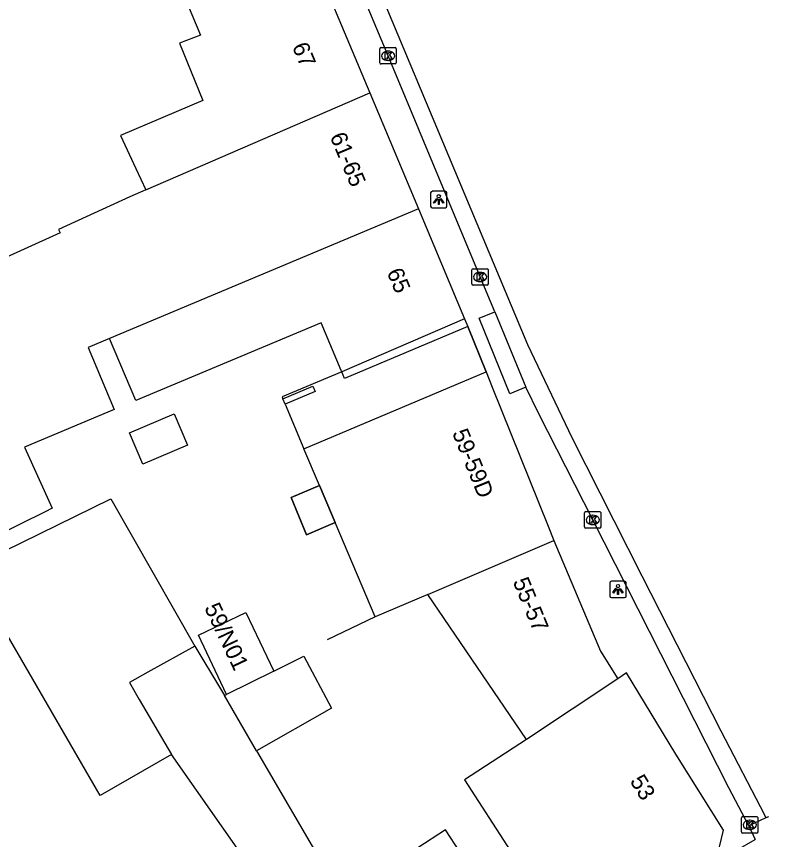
# Model space of a CAD drawing. Extents: x 159377 to 159983, y 382996 to 383595.
# Drawn here: x 159936.99 to 159982.64, y 383295.81 to 383345.77 of the extents above; entities that cross this region are included whole.
import ezdxf

# ---------------------------------------------------------------- set-up
doc = ezdxf.new("R2010")
doc.units = 0
for name, color, linetype in [('IMGEO_Kolk', 7, 'Continuous'), ('IMGEO_Lichtpunt', 7, 'Continuous'), ('IMGEO_Muur', 7, 'Continuous'), ('IMGEO_Pand', 7, 'Continuous'), ('IMGEO_Pand_nummerreeks', 7, 'Continuous'), ('IMGEO_Pand_overbouw', 7, 'Continuous'), ('IMGEO_Rijbaan_lokaal_gesloten', 7, 'Continuous'), ('IMGEO_Rijbaan_lokaal_open', 7, 'Continuous'), ('IMGEO_Voetpad_open', 7, 'Continuous')]:
    doc.layers.add(name, color=color, linetype=linetype)

msp = doc.modelspace()

# ---------------------------------------------------------------- linework, layer by layer
at = {"layer": 'IMGEO_Kolk'}
for p, q in [((159959.042, 383342.956), (159959.042, 383343.808)), ((159959.117, 383343.882), (159959.969, 383343.882)), ((159959.53, 383343.662), (159959.555, 383343.662)), ((159960.043, 383343.808), (159960.043, 383342.956)), ((159959.553, 383343.102), (159959.528, 383343.102)), ((159959.969, 383342.882), (159959.117, 383342.882)), ((159964.627, 383329.53), (159964.627, 383330.382)), ((159964.702, 383330.456), (159965.554, 383330.456)), ((159965.115, 383330.236), (159965.14, 383330.236)), ((159965.628, 383330.382), (159965.628, 383329.53)), ((159965.138, 383329.676), (159965.113, 383329.676)), ((159965.554, 383329.456), (159964.702, 383329.456)), ((159971.466, 383314.783), (159971.466, 383315.635)), ((159971.541, 383315.709), (159972.393, 383315.709)), ((159972.467, 383315.635), (159972.467, 383314.783)), ((159971.954, 383315.489), (159971.979, 383315.489)), ((159972.393, 383314.709), (159971.541, 383314.709)), ((159971.977, 383314.929), (159971.952, 383314.929)), ((159980.996, 383296.27), (159980.996, 383297.122)), ((159981.071, 383297.196), (159981.923, 383297.196)), ((159981.997, 383297.122), (159981.997, 383296.27)), ((159981.484, 383296.976), (159981.509, 383296.976)), ((159981.923, 383296.196), (159981.071, 383296.196)), ((159981.507, 383296.416), (159981.482, 383296.416))]:
    msp.add_line(p, q, dxfattribs=at)
for points in [[(159959.042, 383342.956), (159959.042, 383343.808)], [(159959.117, 383343.882), (159959.969, 383343.882)], [(159959.363, 383343.582), (159959.486, 383343.582), (159959.486, 383343.431), (159959.616, 383343.582), (159959.78, 383343.582), (159959.634, 383343.431), (159959.787, 383343.182), (159959.635, 383343.182), (159959.55, 383343.346), (159959.486, 383343.279), (159959.486, 383343.182), (159959.363, 383343.182), (159959.363, 383343.582)], [(159960.043, 383343.808), (159960.043, 383342.956)], [(159959.969, 383342.882), (159959.117, 383342.882)], [(159964.627, 383329.53), (159964.627, 383330.382)], [(159964.702, 383330.456), (159965.554, 383330.456)], [(159964.948, 383330.156), (159965.071, 383330.156), (159965.071, 383330.005), (159965.201, 383330.156), (159965.365, 383330.156), (159965.219, 383330.005), (159965.372, 383329.756), (159965.22, 383329.756), (159965.135, 383329.92), (159965.071, 383329.853), (159965.071, 383329.756), (159964.948, 383329.756), (159964.948, 383330.156)], [(159965.628, 383330.382), (159965.628, 383329.53)], [(159965.554, 383329.456), (159964.702, 383329.456)], [(159971.466, 383314.783), (159971.466, 383315.635)], [(159971.541, 383315.709), (159972.393, 383315.709)], [(159972.467, 383315.635), (159972.467, 383314.783)], [(159971.787, 383315.409), (159971.91, 383315.409), (159971.91, 383315.258), (159972.04, 383315.409), (159972.204, 383315.409), (159972.058, 383315.258), (159972.211, 383315.009), (159972.059, 383315.009), (159971.974, 383315.173), (159971.91, 383315.106), (159971.91, 383315.009), (159971.787, 383315.009), (159971.787, 383315.409)], [(159972.393, 383314.709), (159971.541, 383314.709)], [(159980.996, 383296.27), (159980.996, 383297.122)], [(159981.071, 383297.196), (159981.923, 383297.196)], [(159981.997, 383297.122), (159981.997, 383296.27)], [(159981.317, 383296.896), (159981.44, 383296.896), (159981.44, 383296.745), (159981.57, 383296.896), (159981.734, 383296.896), (159981.588, 383296.745), (159981.741, 383296.496), (159981.589, 383296.496), (159981.504, 383296.66), (159981.44, 383296.593), (159981.44, 383296.496), (159981.317, 383296.496), (159981.317, 383296.896)], [(159981.923, 383296.196), (159981.071, 383296.196)]]:
    msp.add_lwpolyline(points, dxfattribs=at)
for centre, start, end in [((159959.119, 383343.806), 91.552, 178.448), ((159959.119, 383343.806), 91.552, 178.448), ((159959.967, 383343.806), 1.552, 88.448), ((159959.967, 383343.806), 1.552, 88.448), ((159959.119, 383342.958), 181.552, 268.448), ((159959.119, 383342.958), 181.552, 268.448), ((159959.967, 383342.958), 271.552, 358.448), ((159959.967, 383342.958), 271.552, 358.448), ((159964.704, 383330.38), 91.552, 178.448), ((159964.704, 383330.38), 91.552, 178.448), ((159965.552, 383330.38), 1.552, 88.448), ((159965.552, 383330.38), 1.552, 88.448), ((159964.704, 383329.532), 181.552, 268.448), ((159964.704, 383329.532), 181.552, 268.448), ((159965.552, 383329.532), 271.552, 358.448), ((159965.552, 383329.532), 271.552, 358.448), ((159971.543, 383315.633), 91.552, 178.448), ((159971.543, 383315.633), 91.552, 178.448), ((159972.391, 383315.633), 1.552, 88.448), ((159972.391, 383315.633), 1.552, 88.448), ((159971.543, 383314.785), 181.552, 268.448), ((159971.543, 383314.785), 181.552, 268.448), ((159972.391, 383314.785), 271.552, 358.448), ((159972.391, 383314.785), 271.552, 358.448), ((159981.073, 383297.12), 91.552, 178.448), ((159981.073, 383297.12), 91.552, 178.448), ((159981.921, 383297.12), 1.552, 88.448), ((159981.921, 383297.12), 1.552, 88.448), ((159981.073, 383296.272), 181.552, 268.448), ((159981.073, 383296.272), 181.552, 268.448), ((159981.921, 383296.272), 271.552, 358.448), ((159981.921, 383296.272), 271.552, 358.448)]:
    msp.add_arc(centre, 0.0765, start, end, dxfattribs=at)
for centre, major_axis, ratio, start_param, end_param in [((159959.529, 383343.382), (-0.387, 0.002), 0.722429, 4.712389, 7.853982), ((159959.554, 383343.382), (-0.39, 0.002), 0.717154, 1.570796, 4.712389), ((159965.114, 383329.956), (-0.387, 0.002), 0.722429, 4.712389, 7.853982), ((159965.139, 383329.956), (-0.39, 0.002), 0.717154, 1.570796, 4.712389), ((159971.953, 383315.209), (-0.387, 0.002), 0.722429, 4.712389, 7.853982), ((159971.978, 383315.209), (-0.39, 0.002), 0.717154, 1.570796, 4.712389), ((159981.483, 383296.696), (-0.387, 0.002), 0.722429, 4.712389, 7.853982), ((159981.508, 383296.696), (-0.39, 0.002), 0.717154, 1.570796, 4.712389)]:
    msp.add_ellipse(centre, major_axis=major_axis, ratio=ratio, start_param=start_param, end_param=end_param, dxfattribs=at)
at = {"layer": 'IMGEO_Lichtpunt'}
for p, q in [((159962.122, 383335.058), (159962.122, 383334.251)), ((159962.122, 383335.058), (159962.122, 383334.251)), ((159963.024, 383335.153), (159962.216, 383335.153)), ((159963.024, 383335.153), (159962.216, 383335.153)), ((159963.118, 383334.251), (159963.118, 383335.058)), ((159963.118, 383334.251), (159963.118, 383335.058)), ((159962.216, 383334.157), (159963.024, 383334.157)), ((159962.216, 383334.157), (159963.024, 383334.157)), ((159973.001, 383311.392), (159973.001, 383310.585)), ((159973.001, 383311.392), (159973.001, 383310.585)), ((159973.903, 383311.487), (159973.095, 383311.487)), ((159973.903, 383311.487), (159973.095, 383311.487)), ((159973.997, 383310.585), (159973.997, 383311.392)), ((159973.997, 383310.585), (159973.997, 383311.392)), ((159973.095, 383310.491), (159973.903, 383310.491)), ((159973.095, 383310.491), (159973.903, 383310.491))]:
    msp.add_line(p, q, dxfattribs=at)
for points in [[(159962.496, 383334.722), (159962.535, 383334.694), (159962.347, 383334.432), (159962.309, 383334.459), (159962.496, 383334.722)], [(159962.598, 383334.674), (159962.645, 383334.674), (159962.645, 383334.352), (159962.598, 383334.352), (159962.598, 383334.674)], [(159962.708, 383334.694), (159962.746, 383334.721), (159962.933, 383334.459), (159962.894, 383334.431), (159962.708, 383334.694)], [(159973.375, 383311.056), (159973.414, 383311.028), (159973.226, 383310.766), (159973.188, 383310.793), (159973.375, 383311.056)], [(159973.477, 383311.008), (159973.524, 383311.008), (159973.524, 383310.686), (159973.477, 383310.686), (159973.477, 383311.008)], [(159973.587, 383311.028), (159973.625, 383311.055), (159973.812, 383310.793), (159973.773, 383310.765), (159973.587, 383311.028)]]:
    msp.add_lwpolyline(points, dxfattribs=at)
for centre in [(159962.621, 383334.856), (159973.5, 383311.19)]:
    msp.add_circle(centre, 0.0994, dxfattribs=at)
for centre, start, end in [((159962.216, 383335.058), 90, 180), ((159962.216, 383335.058), 90, 180), ((159963.024, 383335.058), 0, 90), ((159963.024, 383335.058), 0, 90), ((159962.216, 383334.251), 180, 270), ((159962.216, 383334.251), 180, 270), ((159963.024, 383334.251), 270, 0), ((159963.024, 383334.251), 270, 360), ((159973.095, 383311.392), 90, 180), ((159973.095, 383311.392), 90, 180), ((159973.903, 383311.392), 0, 90), ((159973.903, 383311.392), 0, 90), ((159973.095, 383310.585), 180, 270), ((159973.095, 383310.585), 180, 270), ((159973.903, 383310.585), 270, 0), ((159973.903, 383310.585), 270, 360)]:
    msp.add_arc(centre, 0.0946, start, end, dxfattribs=at)
at = {"layer": 'IMGEO_Muur'}
msp.add_lwpolyline([(159958.755, 383309.324), (159955.838, 383307.922)], dxfattribs=at)
at = {"layer": 'IMGEO_Pand'}
for points in [[(159952.848, 383354.454), (159955.649, 383347.779), (159958.438, 383341.13)], [(159945.365, 383351.314), (159948.165, 383344.639), (159946.882, 383344.151), (159948.29, 383340.671), (159943.299, 383338.535), (159944.236, 383336.532), (159944.843, 383335.234)], [(159944.843, 383335.234), (159958.438, 383341.13)], [(159958.438, 383341.13), (159961.392, 383334.091)], [(159944.843, 383335.234), (159943.863, 383334.809), (159939.54, 383332.832), (159939.633, 383332.626), (159933.064, 383329.657), (159932.987, 383329.817)], [(159961.392, 383334.091), (159942.64, 383326.223)], [(159961.392, 383334.091), (159964.191, 383327.419)], [(159956.726, 383324.201), (159956.696, 383324.274), (159955.478, 383327.179), (159944.228, 383322.46), (159942.64, 383326.223)], [(159964.191, 383327.419), (159956.726, 383324.201)], [(159964.191, 383327.419), (159964.378, 383326.953)], [(159964.378, 383326.953), (159956.901, 383323.786), (159956.726, 383324.201)], [(159942.64, 383326.223), (159941.338, 383325.677), (159942.926, 383321.914), (159937.464, 383319.623), (159939.155, 383315.913), (159938.725, 383315.702), (159934.236, 383313.5)], [(159955.38, 383317.291), (159954.438, 383319.517), (159965.489, 383324.198)], [(159965.489, 383324.198), (159965.863, 383323.269), (159969.264, 383314.829), (159969.612, 383313.966)], [(159953.299, 383322.228), (159953.163, 383322.55), (159954.981, 383323.32), (159955.117, 383322.998), (159953.299, 383322.228)], [(159943.845, 383320.503), (159946.558, 383321.648), (159947.362, 383319.744), (159944.649, 383318.599), (159943.845, 383320.503)], [(159955.38, 383317.291), (159956.332, 383315.043)], [(159934.071, 383312.263), (159942.713, 383316.486), (159947.811, 383307.547)], [(159961.953, 383310.678), (159958.755, 383309.324), (159956.332, 383315.043)], [(159961.953, 383310.678), (159969.612, 383313.966)], [(159969.612, 383313.966), (159972.441, 383307.245), (159973.493, 383305.565)], [(159967.948, 383301.873), (159961.953, 383310.678)], [(159949.745, 383304.614), (159948.027, 383308.209), (159950.905, 383309.585), (159952.605, 383306.029)], [(159946.404, 383300.967), (159942.065, 383298.484), (159936.196, 383308.615)], [(159947.811, 383307.547), (159944.953, 383305.96), (159943.837, 383305.341), (159944.439, 383304.314), (159946.404, 383300.967)], [(159947.811, 383307.547), (159949.364, 383304.957), (159949.605, 383304.544)], [(159952.605, 383306.029), (159954.438, 383306.935), (159956.105, 383303.788), (159951.562, 383301.19)], [(159952.605, 383306.029), (159949.745, 383304.614)], [(159979.443, 383294.433), (159979.906, 383296.377), (159977.007, 383300.995), (159974.015, 383305.934), (159973.493, 383305.565)], [(159973.493, 383305.565), (159967.948, 383301.873)], [(159949.605, 383304.544), (159949.745, 383304.614)], [(159951.562, 383301.19), (159949.605, 383304.544)], [(159967.948, 383301.873), (159964.186, 383299.423), (159966.951, 383295.149)], [(159951.562, 383301.19), (159955.785, 383293.954), (159952.607, 383292.1), (159946.404, 383300.967)], [(159966.951, 383295.149), (159964.76, 383293.732), (159963.033, 383296.402), (159961.344, 383295.309)]]:
    msp.add_lwpolyline(points, dxfattribs=at)
at = {"layer": 'IMGEO_Pand_overbouw'}
for points in [[(159956.726, 383324.201), (159953.109, 383322.679), (159953.163, 383322.55), (159954.981, 383323.32), (159955.117, 383322.998), (159953.299, 383322.228), (159954.438, 383319.517), (159965.489, 383324.198), (159964.378, 383326.953), (159956.901, 383323.786)], [(159955.38, 383317.291), (159953.652, 383316.559), (159954.597, 383314.308), (159956.332, 383315.043)]]:
    msp.add_lwpolyline(points, close=True, dxfattribs=at)
at = {"layer": 'IMGEO_Rijbaan_lokaal_gesloten'}
for points in [[(159966.033, 383327.842), (159965.129, 383329.956), (159959.545, 383343.383), (159955.098, 383353.99), (159949.547, 383367.357), (159943.997, 383380.769), (159943.844, 383381.078)], [(159944.818, 383381.47), (159945.45, 383379.953), (159955.349, 383356.123), (159967.997, 383325.865), (159970.698, 383320.214), (159974.947, 383311.811), (159979.747, 383302.409), (159982.396, 383297.308), (159982.474, 383297.117)], [(159966.033, 383327.842), (159967.899, 383323.262)], [(159981.447, 383296.649), (159980.218, 383298.949), (159971.968, 383315.21), (159968.686, 383321.639), (159967.899, 383323.262)]]:
    msp.add_lwpolyline(points, dxfattribs=at)
at = {"layer": 'IMGEO_Rijbaan_lokaal_open'}
for points in [[(159982.474, 383297.117), (159981.447, 383296.649)], [(159982.637, 383297.191), (159982.474, 383297.117)], [(159981.447, 383296.649), (159981.823, 383295.807)]]:
    msp.add_lwpolyline(points, dxfattribs=at)
at = {"layer": 'IMGEO_Voetpad_open'}
for points in [[(159967.899, 383323.262), (159966.936, 383322.87), (159965.07, 383327.45), (159966.033, 383327.842)], [(159964.378, 383326.953), (159965.489, 383324.198)], [(159956.332, 383315.043), (159954.597, 383314.308), (159953.652, 383316.559), (159955.38, 383317.291)], [(159979.443, 383294.433), (159981.823, 383295.807)]]:
    msp.add_lwpolyline(points, dxfattribs=at)

# ---------------------------------------------------------------- texts
at = {"layer": 'IMGEO_Pand_nummerreeks'}
for s, rotation, p in [('67', 292.7577, (159953.7, 383343.948)), ('61-65', 292.7634, (159955.991, 383338.486)), ('65', 292.7577, (159959.448, 383330.248)), ('59-59D', 292.1618, (159963.417, 383320.496)), ('55-57', 292.4136, (159967.098, 383311.471)), ('59/N01', 295.3875, (159948.368, 383309.878)), ('53', 301.4437, (159974.193, 383299.358))]:
    msp.add_text(s, height=1, rotation=rotation, dxfattribs=at).set_placement(p)

doc.saveas('drawing.dxf')
